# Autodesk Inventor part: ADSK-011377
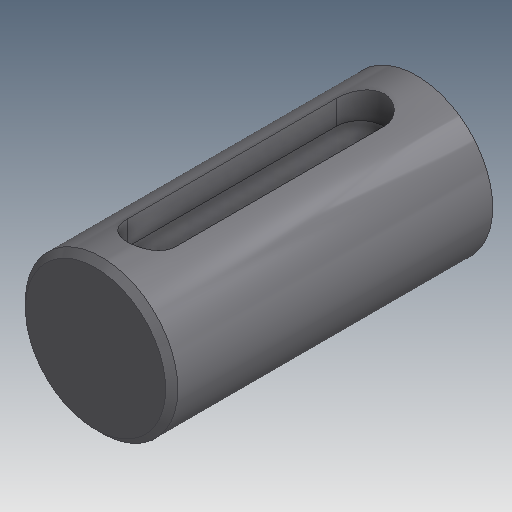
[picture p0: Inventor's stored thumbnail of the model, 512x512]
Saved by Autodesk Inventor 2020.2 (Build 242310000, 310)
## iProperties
Created: 1999-12
Part Number: ADSK-011377
Document SubType Name: Modeling
Designer: tgregory
Material: Pearson CD 1018
Density: 7.83 g/cm^3
Appearance: Metal-Steel(Polish)
Mass: 83.8417 g
Surface Area: 31.425 cm^2
Volume: 10.7078 cm^3
Control State: 0
Master: False
Checked Out: False
Shininess: 60.0
Length Units: 11272
Angle Units: 11279
Time Units: 11290
Mass Units: 11286
Length Display Precision: 3
Angle Display Precision: 2
Compacted: True
Dimensions: 0,7x1,6x0,7 in
Mass: 0,185 lb
VLT_Material: Pearson CD 1018
Density: 7.829999999999999
Volumn: 10.58742530620839
Area: 31.778307021259096
PropertySet Name: Model Information
Author: tgregory
Revision Number: -
Title: ADSK-011377
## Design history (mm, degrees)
node "Extrusion1" dims "d3" = 40, "d4" = 0
node "Chamfer1" dims "d5" = 0.762, "d6" = 0.762, "d27" = 45 deg
workplane "Work Plane1"
node "Extrusion3" dims "d25" = 3.5, "d26" = 0
node "Solide1"
node "Corps solides"
node "Corps surfaciques"
sketch "Sketch1"
  geometry: C1 r 9.5 at (0, 0); 1 further point
  constraints: 1 centre point, 1 coincident
  dimensions: "d0" = 19 diameter of C1
sketch "Sketch3"
  geometry: L1 (-8.738, 40)-(8.738, 40) reference; L2 (0, 0.4)-(0, 50.8) reference; L3 (-3, 33)-(-3, 7); L4 (3, 33)-(3, 7); A1 r 3 centre (0, 33) between (-3, 33) and (3, 33); A2 r 3 centre (0, 7) between (-3, 7) and (3, 7)
  constraints: 4 end point, 4 point on circle, 3 tangent, 2 centre point, 2 point on line, 1 equal radius, 1 parallel
  dimensions: "d22" = 6 diameter of A1; "d23" = 26 distance of A2.centre A1.centre; "d24" = 7 distance from line of L1 A1.centre
other parameters: "d21" = 9.5 (= 0.5 x d0)
